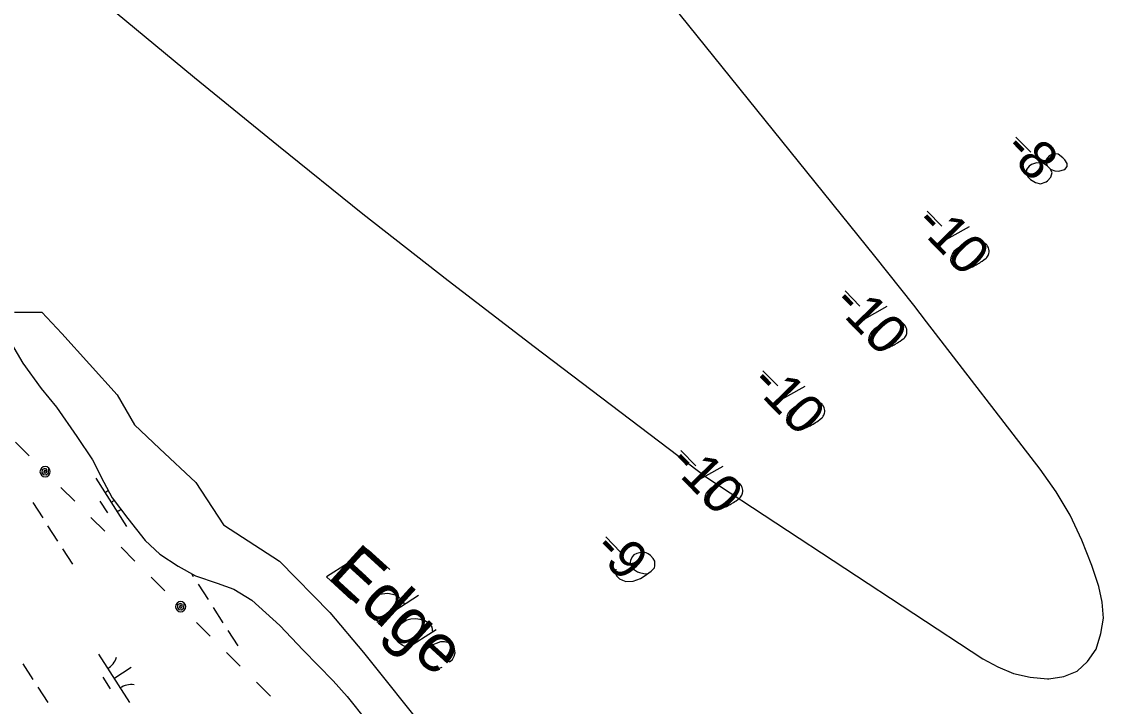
# Model space of a CAD drawing. Extents: x 3962991 to 3983549, y 181631 to 204078.
# Drawn here: x 3974291 to 3975236, y 192679 to 193277 of the extents above; entities that cross this region are included whole.
import ezdxf

# ---------------------------------------------------------------- set-up
doc = ezdxf.new("R2010")
doc.units = 0
for name, color, linetype in [('V-ANNO-MASK', 7, 'Continuous'), ('V-ANNO-MASK2', 7, 'Continuous'), ('V-RIVR-EDGE', 7, 'Continuous'), ('V-RIVR-IDEN', 7, 'Continuous'), ('V-RIVR-RANG', 7, 'Continuous'), ('V-TOPO-DPTH', 7, 'Continuous'), ('V-TOPO-MINR', 7, 'Continuous'), ('V-UTIL-LINE', 7, 'Continuous'), ('V-WETL-SWMP', 7, 'Continuous')]:
    doc.layers.add(name, color=color, linetype=linetype)

msp = doc.modelspace()

# ---------------------------------------------------------------- linework, layer by layer
at = {"layer": 'V-ANNO-MASK2'}
for p, q in [((3975159.38, 193176.47), (3975172.25, 193163.23)), ((3975081.85, 193111.89), (3975094.72, 193098.66)), ((3975118.41, 193098.14), (3975088.14, 193081.21)), ((3975010.17, 193042.16), (3975023.05, 193028.92)), ((3975046.73, 193028.41), (3975016.47, 193011.48)), ((3974938.5, 192972.42), (3974951.38, 192959.19)), ((3974975.06, 192958.68), (3974944.8, 192941.74)), ((3974866.9, 192902.76), (3974879.77, 192889.52)), ((3974903.46, 192889.01), (3974873.19, 192872.08)), ((3974801.21, 192827.44), (3974814.09, 192814.21)), ((3974578.01, 192805.63), (3974592.18, 192792.7)), ((3974637.64, 192776.28), (3974601.26, 192752.61))]:
    msp.add_line(p, q, dxfattribs=at)
for points in [[(3975186.64, 193151.47), (3975189.22, 193148.82), (3975190.14, 193148.25), (3975193.3, 193146.9), (3975196.46, 193146.67), (3975201.9, 193148.28), (3975204.17, 193150.86), (3975204.02, 193153.28), (3975202.01, 193156.48), (3975200.17, 193158.37), (3975196.11, 193161.41), (3975193.5, 193161.82), (3975190.51, 193161.12), (3975188.25, 193160.03), (3975185.78, 193156.89), (3975185.39, 193155.03), (3975186.64, 193151.47), (3975182.94, 193153.76), (3975177.35, 193153.83), (3975173.04, 193152.59), (3975170.97, 193150.94), (3975168.5, 193148.17), (3975168.27, 193144.63), (3975169.72, 193141.63), (3975171.93, 193139.36), (3975176.37, 193136.69), (3975180.64, 193135.7), (3975185.7, 193137.3), (3975187.02, 193138.22), (3975189.86, 193141.35), (3975191.04, 193145.44), (3975189.22, 193148.82)], [(3975133.86, 193082.26), (3975133.49, 193082.64), (3975132.2, 193083.59), (3975131.27, 193084.16), (3975130.53, 193084.55), (3975129.23, 193085.13), (3975127.56, 193085.71), (3975126.08, 193086.1), (3975124.4, 193086.31), (3975123.09, 193086.14), (3975121.6, 193085.79), (3975120.1, 193085.44), (3975118.41, 193084.9), (3975117.29, 193084.54), (3975115.79, 193083.82), (3975113.34, 193082.55), (3975109.96, 193080.35), (3975107.32, 193078.52), (3975105.24, 193076.5), (3975103.91, 193074.84), (3975102.95, 193072.43), (3975102.55, 193070.94), (3975102.34, 193068.89), (3975102.68, 193067.02), (3975103.05, 193066.27), (3975103.96, 193064.95), (3975104.88, 193064.01), (3975106.54, 193062.68), (3975108.21, 193061.72), (3975109.69, 193061.33), (3975111.93, 193060.93), (3975113.05, 193060.91), (3975114.54, 193060.89), (3975115.85, 193061.06), (3975116.78, 193061.23), (3975118.1, 193061.77), (3975118.66, 193061.95), (3975119.97, 193062.49), (3975121.47, 193063.22), (3975122.98, 193063.95), (3975123.92, 193064.49), (3975124.67, 193064.86), (3975125.61, 193065.4), (3975127.68, 193066.68), (3975128.81, 193067.41), (3975129.93, 193068.14), (3975131.44, 193069.24), (3975133.33, 193070.71), (3975133.89, 193071.26), (3975134.47, 193072.18), (3975135.04, 193073.11), (3975135.62, 193074.78), (3975135.83, 193076.08), (3975135.84, 193077.2), (3975135.67, 193078.51), (3975135.32, 193079.63), (3975134.95, 193080.38), (3975134.59, 193081.13), (3975133.86, 193082.26)], [(3975062.19, 193012.53), (3975061.82, 193012.91), (3975060.52, 193013.86), (3975059.6, 193014.43), (3975058.86, 193014.81), (3975057.56, 193015.39), (3975055.89, 193015.97), (3975054.4, 193016.37), (3975052.73, 193016.58), (3975051.42, 193016.41), (3975049.92, 193016.06), (3975048.42, 193015.7), (3975046.74, 193015.17), (3975045.61, 193014.81), (3975044.11, 193014.08), (3975041.67, 193012.81), (3975038.28, 193010.62), (3975035.65, 193008.79), (3975033.57, 193006.77), (3975032.24, 193005.11), (3975031.27, 193002.69), (3975030.88, 193001.21), (3975030.66, 192999.16), (3975031.01, 192997.29), (3975031.37, 192996.54), (3975032.29, 192995.22), (3975033.21, 192994.27), (3975034.87, 192992.94), (3975036.53, 192991.99), (3975038.02, 192991.6), (3975040.25, 192991.19), (3975041.37, 192991.18), (3975042.87, 192991.16), (3975044.17, 192991.32), (3975045.11, 192991.5), (3975046.42, 192992.04), (3975046.98, 192992.22), (3975048.3, 192992.76), (3975049.8, 192993.49), (3975051.3, 192994.21), (3975052.24, 192994.76), (3975052.99, 192995.12), (3975053.93, 192995.67), (3975056, 192996.95), (3975057.13, 192997.68), (3975058.26, 192998.41), (3975059.77, 192999.5), (3975061.65, 193000.97), (3975062.22, 193001.52), (3975062.79, 193002.45), (3975063.37, 193003.37), (3975063.95, 193005.04), (3975064.15, 193006.35), (3975064.17, 193007.47), (3975064, 193008.77), (3975063.64, 193009.9), (3975063.28, 193010.65), (3975062.92, 193011.4), (3975062.19, 193012.53)], [(3974990.51, 192942.8), (3974990.14, 192943.17), (3974988.85, 192944.12), (3974987.93, 192944.7), (3974987.18, 192945.08), (3974985.89, 192945.66), (3974984.22, 192946.24), (3974982.73, 192946.63), (3974981.05, 192946.84), (3974979.75, 192946.67), (3974978.25, 192946.32), (3974976.75, 192945.97), (3974975.06, 192945.43), (3974973.94, 192945.07), (3974972.44, 192944.35), (3974970, 192943.08), (3974966.61, 192940.88), (3974963.97, 192939.06), (3974961.89, 192937.03), (3974960.56, 192935.37), (3974959.6, 192932.96), (3974959.2, 192931.47), (3974958.99, 192929.42), (3974959.34, 192927.55), (3974959.7, 192926.8), (3974960.61, 192925.48), (3974961.53, 192924.54), (3974963.19, 192923.21), (3974964.86, 192922.25), (3974966.35, 192921.86), (3974968.58, 192921.46), (3974969.7, 192921.44), (3974971.19, 192921.42), (3974972.5, 192921.59), (3974973.43, 192921.76), (3974974.75, 192922.31), (3974975.31, 192922.48), (3974976.62, 192923.03), (3974978.13, 192923.75), (3974979.63, 192924.48), (3974980.57, 192925.02), (3974981.32, 192925.39), (3974982.26, 192925.93), (3974984.33, 192927.21), (3974985.46, 192927.94), (3974986.59, 192928.67), (3974988.09, 192929.77), (3974989.98, 192931.24), (3974990.55, 192931.79), (3974991.12, 192932.71), (3974991.69, 192933.64), (3974992.27, 192935.31), (3974992.48, 192936.61), (3974992.49, 192937.73), (3974992.33, 192939.04), (3974991.97, 192940.16), (3974991.6, 192940.91), (3974991.24, 192941.67), (3974990.51, 192942.8)], [(3974918.91, 192873.13), (3974918.54, 192873.51), (3974917.25, 192874.46), (3974916.32, 192875.03), (3974915.58, 192875.41), (3974914.29, 192875.99), (3974912.61, 192876.57), (3974911.13, 192876.97), (3974909.45, 192877.18), (3974908.14, 192877.01), (3974906.65, 192876.66), (3974905.15, 192876.3), (3974903.46, 192875.77), (3974902.34, 192875.41), (3974900.84, 192874.68), (3974898.39, 192873.41), (3974895.01, 192871.22), (3974892.37, 192869.39), (3974890.29, 192867.37), (3974888.96, 192865.71), (3974888, 192863.3), (3974887.6, 192861.81), (3974887.39, 192859.76), (3974887.73, 192857.89), (3974888.1, 192857.14), (3974889.01, 192855.82), (3974889.93, 192854.87), (3974891.59, 192853.55), (3974893.26, 192852.59), (3974894.75, 192852.2), (3974896.98, 192851.79), (3974898.1, 192851.78), (3974899.59, 192851.76), (3974900.9, 192851.93), (3974901.83, 192852.1), (3974903.15, 192852.64), (3974903.71, 192852.82), (3974905.02, 192853.36), (3974906.52, 192854.09), (3974908.03, 192854.81), (3974908.97, 192855.36), (3974909.72, 192855.72), (3974910.66, 192856.27), (3974912.73, 192857.55), (3974913.86, 192858.28), (3974914.98, 192859.01), (3974916.49, 192860.11), (3974918.38, 192861.57), (3974918.94, 192862.12), (3974919.52, 192863.05), (3974920.09, 192863.97), (3974920.67, 192865.65), (3974920.88, 192866.95), (3974920.89, 192868.07), (3974920.72, 192869.38), (3974920.37, 192870.5), (3974920, 192871.25), (3974919.64, 192872), (3974918.91, 192873.13)], [(3974612.73, 192799.02), (3974594.16, 192815.96), (3974557.54, 192792.52), (3974579.04, 192772.9)], [(3974810.16, 192799.34), (3974809.55, 192795.8), (3974810.64, 192793.55), (3974813.21, 192790.9), (3974815.81, 192789.75), (3974817.29, 192788.98), (3974818.77, 192788.59), (3974825.12, 192788.87), (3974831.68, 192791.21), (3974834.69, 192793.03), (3974840.91, 192797.61), (3974843.75, 192800.37), (3974844.14, 192802.23), (3974844.19, 192805.21), (3974844.01, 192806.15), (3974842.74, 192808.59), (3974840.35, 192811.05), (3974838.13, 192812.57), (3974836.47, 192813.53), (3974833.11, 192813.95), (3974828.25, 192812.89), (3974825.81, 192811.62), (3974824.29, 192810.15), (3974822.76, 192806.81), (3974822.55, 192805.14), (3974823.08, 192803.08), (3974824.72, 192800.26), (3974826.37, 192798.56), (3974828.96, 192797.03), (3974830.82, 192796.26), (3974834.54, 192795.46), (3974836.59, 192795.24), (3974837.71, 192795.23)], [(3974625.59, 192768.47), (3974624.77, 192771.01), (3974620.62, 192774.8), (3974617.73, 192776.54), (3974611.1, 192778.11), (3974603.43, 192777.06), (3974597.48, 192773.98), (3974595.01, 192771.76), (3974593.47, 192769.58), (3974592.64, 192767.2), (3974592.32, 192763.91), (3974592.92, 192761.13), (3974595.16, 192758.19), (3974597.34, 192756.65), (3974599.51, 192755.11), (3974603.54, 192754.12)], [(3974628.72, 192730.69), (3974626.34, 192731.52), (3974623.47, 192732.79), (3974620.32, 192735.22), (3974618.1, 192737.7), (3974617.7, 192741.19), (3974617.82, 192743.77), (3974618.18, 192746.13), (3974619.48, 192748.53), (3974621.93, 192751.22), (3974624.42, 192752.97), (3974627.61, 192754.99), (3974631.08, 192755.85), (3974635.29, 192756.04), (3974639.04, 192755.74), (3974643.31, 192754.53), (3974646.69, 192752.34), (3974649.44, 192748.49), (3974650.1, 192744.31)], [(3974653.28, 192746.33), (3974626.67, 192729.43), (3974623.68, 192728.12), (3974620.92, 192727.06), (3974618.59, 192726.95), (3974614.58, 192727.47), (3974610.03, 192729.84), (3974607.77, 192733.25), (3974607.19, 192735.56)], [(3974649.23, 192732.56), (3974664.86, 192718.29), (3974667.34, 192720.51), (3974668.85, 192723.16), (3974669.88, 192726.25), (3974668.96, 192731.12), (3974666.74, 192733.6), (3974664.34, 192734.89), (3974660.32, 192735.88), (3974657.05, 192735.73), (3974653.13, 192734.38), (3974650.37, 192733.32), (3974645.6, 192730.06), (3974643.15, 192727.37), (3974641.38, 192724.95), (3974640.33, 192722.33), (3974640.81, 192716.96), (3974642.54, 192714.94), (3974644.72, 192713.4), (3974644.96, 192713.17), (3974649.48, 192711.74), (3974652.75, 192711.89), (3974654.6, 192712.44), (3974655.06, 192712.46), (3974658.29, 192713.55)]]:
    msp.add_lwpolyline(points, dxfattribs=at)
at = {"layer": 'V-RIVR-EDGE'}
msp.add_lwpolyline([(3974285, 193023.49), (3974309.02, 193023.49), (3974326.5, 193004.92), (3974374.55, 192951.4), (3974389.84, 192925.19), (3974411.69, 192904.44), (3974443.36, 192874.95), (3974467.39, 192837.82), (3974516.53, 192806.15), (3974560.22, 192761.37), (3974589.71, 192726.42), (3974646.5, 192655.43)], dxfattribs=at)
at = {"layer": 'V-TOPO-DPTH'}
msp.add_lwpolyline([(3974271.51, 193369.82), (3974442.17, 193228.56), (3974515.44, 193168.7), (3974589.22, 193109.47), (3974663.75, 193051.19), (3974738.79, 192993.55), (3974889.61, 192879.22), (3975130.32, 192721.03), (3975143.56, 192713.86), (3975157.3, 192708.27), (3975171.78, 192705.05), (3975186.76, 192703.42), (3975188.19, 192703.39), (3975201.25, 192705.55), (3975212.72, 192710.21), (3975221.81, 192718.61), (3975229.32, 192729.52), (3975233.51, 192743.01), (3975235.67, 192756.6), (3975234.75, 192770.32), (3975231.8, 192784.14), (3975225.69, 192802.3), (3975216.89, 192824.69), (3975206.67, 192846.34), (3975194.35, 192866.85), (3975180.62, 192886.62), (3975081.35, 193015.18), (3975070.16, 193029.59), (3975058.9, 193043.96), (3975047.55, 193058.25), (3975036.15, 193072.49), (3974725.93, 193457.49)], dxfattribs=at)
at = {"layer": 'V-TOPO-MINR'}
msp.add_lwpolyline([(3974271.51, 193369.82), (3974442.17, 193228.56), (3974515.44, 193168.7), (3974589.22, 193109.47), (3974663.75, 193051.19), (3974738.79, 192993.55), (3974889.61, 192879.22), (3975130.32, 192721.03), (3975143.56, 192713.86), (3975157.3, 192708.27), (3975171.78, 192705.05), (3975186.76, 192703.42), (3975188.19, 192703.39), (3975201.25, 192705.55), (3975212.72, 192710.21), (3975221.81, 192718.61), (3975229.32, 192729.52), (3975233.51, 192743.01), (3975235.67, 192756.6), (3975234.75, 192770.32), (3975231.8, 192784.14), (3975225.69, 192802.3), (3975216.89, 192824.69), (3975206.67, 192846.34), (3975194.35, 192866.85), (3975180.62, 192886.62), (3975081.35, 193015.18), (3975070.16, 193029.59), (3975058.9, 193043.96), (3975047.55, 193058.25), (3975036.15, 193072.49), (3974725.93, 193457.49)], dxfattribs=at)
at = {"layer": 'V-UTIL-LINE'}
for points in [[(3974285.94, 192910.1), (3974297.99, 192898.1)], [(3974311.79, 192884.35), (3974312.05, 192885.77), (3974310.99, 192885.28), (3974310.78, 192883.92), (3974311.93, 192883.01), (3974313.18, 192884.16), (3974313.23, 192886.5), (3974311.23, 192887.24), (3974309.12, 192886.04), (3974309.01, 192883.75), (3974310.21, 192881.87), (3974312.61, 192881.64), (3974314.67, 192883.48), (3974314.97, 192887.54), (3974313.51, 192888.52), (3974311.78, 192888.85), (3974310.06, 192888.51), (3974308.6, 192887.53), (3974307.63, 192886.07), (3974307.29, 192884.34), (3974307.64, 192882.62), (3974308.62, 192881.17), (3974310.08, 192880.19), (3974311.8, 192879.85), (3974313.52, 192880.2), (3974314.98, 192881.18), (3974315.95, 192882.64), (3974316.29, 192884.36), (3974315.95, 192886.08), (3974314.97, 192887.54)], [(3974325.62, 192870.58), (3974337.66, 192858.58)], [(3974351.83, 192844.47), (3974363.88, 192832.47)], [(3974378.05, 192818.36), (3974390.1, 192806.36)], [(3974404.27, 192792.25), (3974416.31, 192780.25)], [(3974430.12, 192766.51), (3974430.37, 192767.92), (3974429.32, 192767.43), (3974429.11, 192766.08), (3974430.25, 192765.16), (3974431.51, 192766.31), (3974431.56, 192768.65), (3974429.56, 192769.39), (3974427.44, 192768.19), (3974427.33, 192765.9), (3974428.54, 192764.02), (3974430.94, 192763.79), (3974432.99, 192765.63), (3974433.29, 192769.69), (3974431.83, 192770.67), (3974430.11, 192771.01), (3974428.39, 192770.66), (3974426.93, 192769.68), (3974425.96, 192768.22), (3974425.62, 192766.5), (3974425.96, 192764.77), (3974426.94, 192763.32), (3974428.4, 192762.34), (3974430.13, 192762.01), (3974431.85, 192762.35), (3974433.3, 192763.33), (3974434.28, 192764.79), (3974434.62, 192766.51), (3974434.27, 192768.24), (3974433.29, 192769.69)], [(3974443.94, 192752.73), (3974455.99, 192740.73)], [(3974470.16, 192726.62), (3974482.2, 192714.62)], [(3974496.38, 192700.51), (3974508.42, 192688.51)]]:
    msp.add_lwpolyline(points, dxfattribs=at)
at = {"layer": 'V-WETL-SWMP'}
for p, q in [((3974355.94, 192878.72), (3974382.92, 192836.62)), ((3974301.03, 192857.42), (3974309.67, 192843.95)), ((3974359.7, 192858.56), (3974366.17, 192848.45)), ((3974369.43, 192857.67), (3974372.02, 192859.33)), ((3974313.98, 192837.21), (3974322.62, 192823.74)), ((3974326.94, 192817.01), (3974335.57, 192803.54)), ((3974439.47, 192795.43), (3974441.14, 192792.82)), ((3974445.46, 192786.09), (3974454.09, 192772.62)), ((3974458.41, 192765.88), (3974467.05, 192752.41)), ((3974471.36, 192745.68), (3974480, 192732.21)), ((3974358.35, 192724.99), (3974385.34, 192682.9)), ((3974292.47, 192716.52), (3974301.11, 192703.05)), ((3974371.85, 192703.94), (3974387, 192713.66)), ((3974362.11, 192704.83), (3974368.59, 192694.73)), ((3974305.43, 192696.31), (3974314.06, 192682.84))]:
    msp.add_line(p, q, dxfattribs=at)
msp.add_lwpolyline([(3974282.39, 192995.87), (3974292.26, 192979.06), (3974308.23, 192956.88), (3974321.71, 192940.72), (3974339.54, 192914.94), (3974353.08, 192894.55), (3974362.97, 192875.32), (3974370.39, 192861.51), (3974383.89, 192843.53), (3974399.23, 192824.37), (3974412.06, 192812.43), (3974427.9, 192801.74), (3974443.1, 192793.45), (3974461.91, 192787.02), (3974476.48, 192781.75), (3974492.31, 192772.27), (3974516.74, 192750.19), (3974536.94, 192728.66), (3974563.24, 192701.77), (3974575.49, 192688.01), (3974592.66, 192666.46)], dxfattribs=at)
for centre, start, end in [((3974354.72, 192881.05), 301.89187, 313.21538), ((3974384.54, 192834.54), 110.83671, 123.43552), ((3974357.14, 192727.33), 301.89187, 343.43553), ((3974386.95, 192680.82), 81.89186, 123.43552)]:
    msp.add_arc(centre, 17.62, start, end, dxfattribs=at)

# ---------------------------------------------------------------- texts
at = {"layer": 'V-ANNO-MASK'}
for s, height, rotation, p in [('-8', 33.5, 314.21389, (3975147.28, 193164.69)), ('-10', 33.5, 314.21389, (3975069.75, 193100.12)), ('-10', 33.5, 314.21389, (3974998.07, 193030.38)), ('-10', 33.5, 314.21389, (3974926.4, 192960.65)), ('-10', 33.5, 314.21389, (3974854.8, 192890.99)), ('-9', 33.5, 314.21389, (3974789.11, 192815.67)), ('Edge', 42, 317.61081, (3974557.54, 192792.52))]:
    msp.add_text(s, height=height, rotation=rotation, dxfattribs=at).set_placement(p)
at = {"layer": 'V-RIVR-IDEN'}
msp.add_text('Edge', height=42, rotation=317.61081, dxfattribs=at).set_placement((3974557.54, 192792.52))
at = {"layer": 'V-RIVR-RANG'}
for s, p in [('-8', (3975147.28, 193164.69)), ('-10', (3975069.75, 193100.12)), ('-10', (3974998.07, 193030.38)), ('-10', (3974926.4, 192960.65)), ('-10', (3974854.8, 192890.99)), ('-9', (3974789.11, 192815.67))]:
    msp.add_text(s, height=33.5, rotation=314.21389, dxfattribs=at).set_placement(p)

doc.saveas('drawing.dxf')
